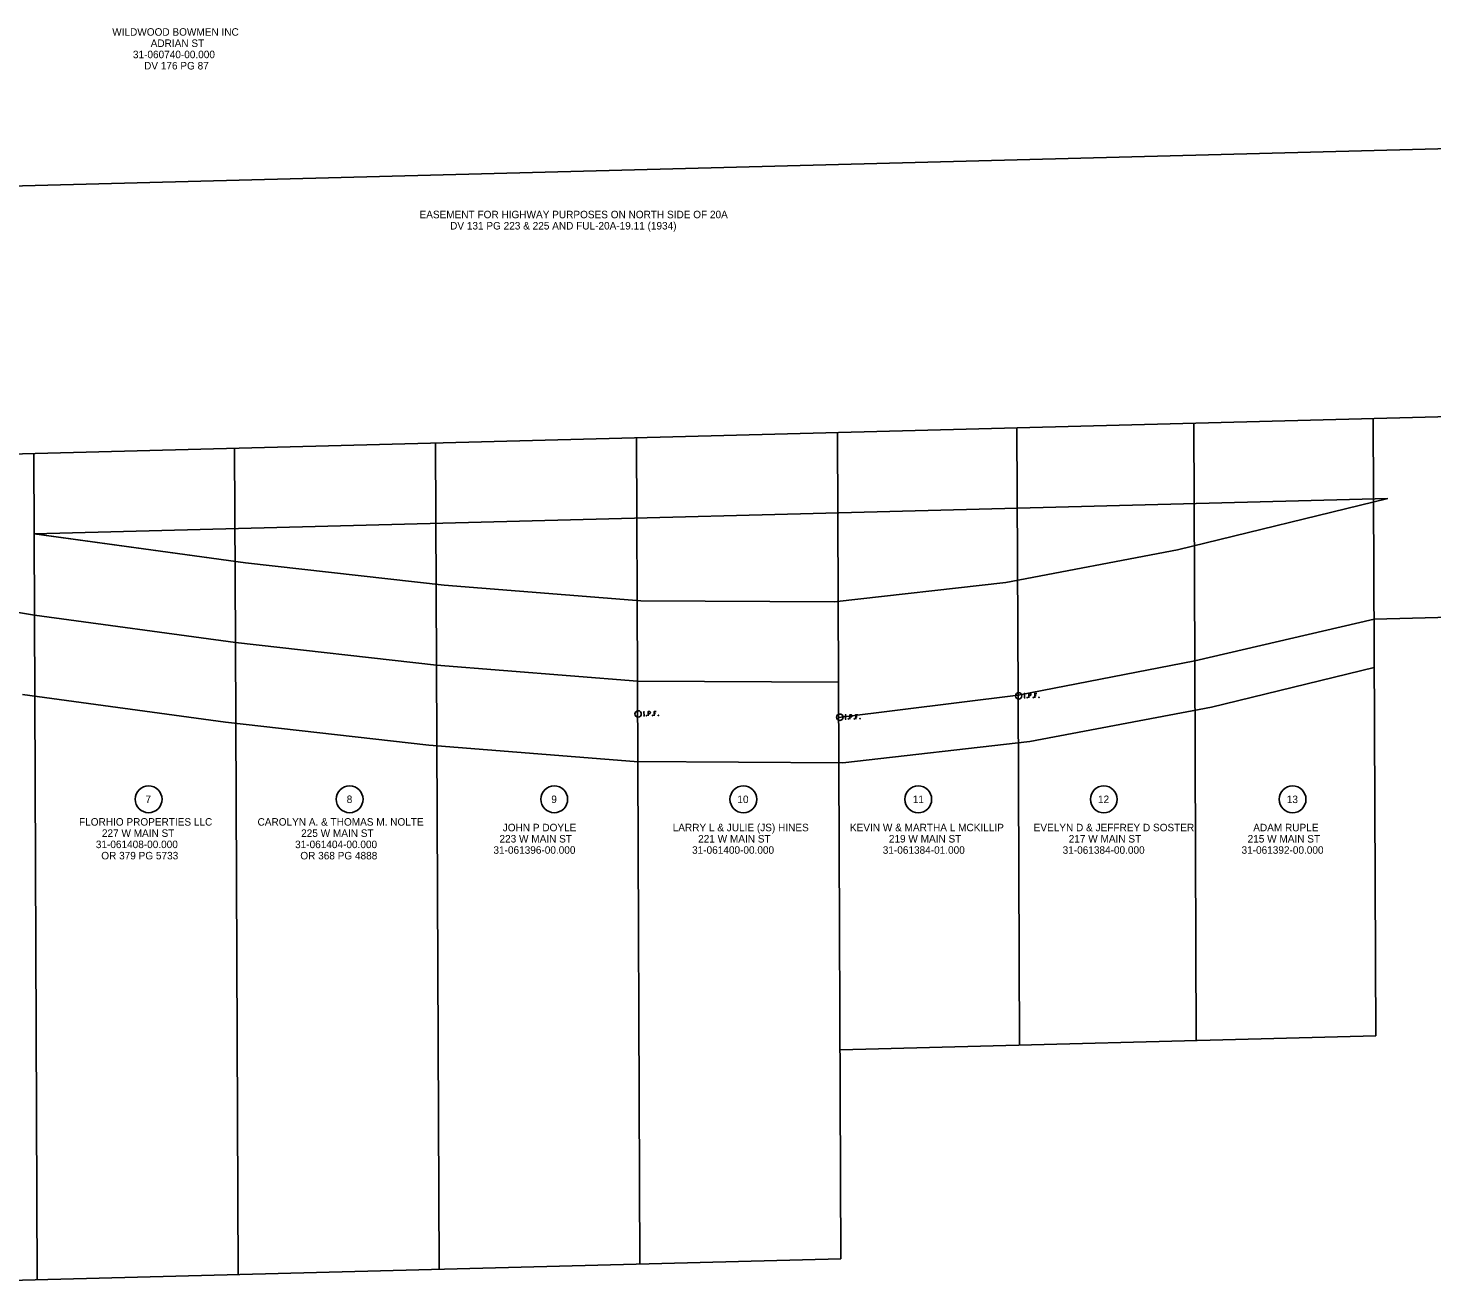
# Model space of a CAD drawing. Extents: x 200073 to 202746, y 352381 to 357578.
# Drawn here: x 200912 to 201436, y 354649 to 355118 of the extents above; entities that cross this region are included whole.
import ezdxf

# ---------------------------------------------------------------- set-up
doc = ezdxf.new("R2010")
doc.units = 0
for name, color, linetype in [('_CIVIL_CONSTRUCTION', 7, 'Continuous'), ('RW_X_CL_100_Bearings', 7, 'Continuous'), ('RW_X_CL_100_Cardinal_Points', 7, 'Continuous'), ('RW_X_CL_100_Stations', 7, 'Continuous'), ('RW_X_CL_500_Bearings', 7, 'Continuous'), ('RW_X_CL_500_Cardinal_Points', 7, 'Continuous'), ('SC_Scratch1', 7, 'Continuous')]:
    doc.layers.add(name, color=color, linetype=linetype)

msp = doc.modelspace()

# ---------------------------------------------------------------- linework, layer by layer
at = {"layer": '_CIVIL_CONSTRUCTION'}
msp.add_line((200083.32, 354937.76), (202745.29, 355007.24), dxfattribs=at)
at = {"layer": 'RW_X_CL_100_Bearings'}
for p, q in [((201281.24, 354869.21), (201280.81, 354969.01)), ((201346.79, 354970.74), (201347.17, 354882.08)), ((201413.77, 354972.48), (201414.76, 354742.08)), ((201138.85, 354965.31), (201139.24, 354874.46)), ((201213.83, 354967.27), (201214.23, 354874.06)), ((200913.92, 354959.44), (200914.18, 354899.14)), ((200988.9, 354961.4), (200989.21, 354888.89)), ((201063.87, 354963.35), (201064.23, 354880.45)), ((200839.14, 354911.48), (200914.18, 354899.14)), ((200914.18, 354899.14), (200915.24, 354651.13)), ((200914.18, 354899.14), (200989.21, 354888.89)), ((201347.17, 354882.08), (201414.09, 354897.58)), ((200989.21, 354888.89), (200990.22, 354653.08)), ((200989.21, 354888.89), (201064.23, 354880.45)), ((201064.23, 354880.45), (201065.19, 354655.04)), ((201064.23, 354880.45), (201139.24, 354874.46)), ((201347.17, 354882.08), (201281.24, 354869.21)), ((201347.17, 354882.08), (201347.78, 354740.33)), ((201139.24, 354874.46), (201140.17, 354657)), ((201139.24, 354874.46), (201214.23, 354874.06)), ((201214.23, 354874.06), (201215.15, 354658.95)), ((201281.24, 354869.21), (201214.29, 354860.86)), ((201281.8, 354738.61), (201281.24, 354869.21)), ((201414.76, 354742.08), (201214.82, 354736.86)), ((201215.15, 354658.95), (200840.26, 354649.17))]:
    msp.add_line(p, q, dxfattribs=at)
at = {"layer": 'RW_X_CL_100_Cardinal_Points'}
for p, q in [((201414.09, 354897.58), (201637.62, 354903.42)), ((201414.17, 354879.62), (201414.09, 354897.58))]:
    msp.add_line(p, q, dxfattribs=at)
at = {"layer": 'RW_X_CL_100_Stations'}
for centre in [(200956.8, 354830.39), (201031.82, 354830.39), (201108.17, 354830.39), (201178.75, 354830.38), (201244, 354830.38), (201313.25, 354830.38), (201383.69, 354830.38)]:
    msp.add_circle(centre, 5, dxfattribs=at)
at = {"layer": 'RW_X_CL_500_Bearings'}
for p, q in [((200731.62, 355054.72), (201543.51, 355075.91)), ((200914.06, 354929.43), (201419.25, 354942.62)), ((201340.76, 354923.48), (201419.24, 354942.62)), ((201340.76, 354923.48), (201419.24, 354942.62)), ((200914.06, 354929.43), (200992.91, 354918.67)), ((200914.74, 354929.45), (200918.64, 354928.81)), ((200918.64, 354928.81), (200992.91, 354918.67)), ((201276.7, 354911.3), (201340.76, 354923.48)), ((201276.7, 354911.3), (201340.76, 354923.48)), ((200992.91, 354918.67), (201067.1, 354910.32)), ((200992.91, 354918.67), (201067.1, 354910.32)), ((201212.62, 354904.07), (201276.7, 354911.3)), ((201212.62, 354904.07), (201276.7, 354911.3)), ((201067.1, 354910.32), (201140.52, 354904.45)), ((201067.1, 354910.32), (201140.52, 354904.45)), ((201140.52, 354904.45), (201212.62, 354904.07)), ((201140.52, 354904.45), (201212.62, 354904.07)), ((201353.48, 354864.82), (201414.17, 354879.62)), ((200909.71, 354869.47), (200985.5, 354859.12)), ((201285.68, 354851.93), (201353.48, 354864.82)), ((200985.5, 354859.12), (201061.36, 354850.58)), ((201061.36, 354850.58), (201137.97, 354844.46)), ((201215.84, 354844.05), (201285.68, 354851.93)), ((201137.97, 354844.46), (201215.84, 354844.05))]:
    msp.add_line(p, q, dxfattribs=at)
at = {"layer": 'SC_Scratch1'}
for points in [[(201283.48, 354869.82), (201283.84, 354869.83)], [(201283.69, 354868.23), (201283.66, 354869.83)], [(201285.26, 354868.26), (201285.23, 354869.86), (201285.75, 354869.87), (201285.81, 354869.85), (201285.89, 354869.83), (201285.92, 354869.81), (201285.95, 354869.78), (201286, 354869.72), (201286.03, 354869.66), (201286.06, 354869.56), (201286.06, 354869.41), (201286.05, 354869.35), (201286.03, 354869.28), (201285.99, 354869.19), (201285.94, 354869.15), (201285.91, 354869.13), (201285.86, 354869.1), (201285.77, 354869.08), (201285.24, 354869.07)], [(201288.23, 354869.91), (201287.47, 354869.9), (201287.5, 354868.3)], [(201287.49, 354869.12), (201288.03, 354869.13)], [(201283.51, 354868.22), (201283.87, 354868.23)], [(201284.65, 354868.46), (201284.7, 354868.46), (201284.73, 354868.44), (201284.77, 354868.39), (201284.77, 354868.32), (201284.74, 354868.27), (201284.71, 354868.25), (201284.65, 354868.24), (201284.62, 354868.27), (201284.58, 354868.32), (201284.58, 354868.38), (201284.61, 354868.43), (201284.65, 354868.46)], [(201286.89, 354868.5), (201286.95, 354868.5), (201286.98, 354868.48), (201287.02, 354868.43), (201287.02, 354868.36), (201286.99, 354868.31), (201286.95, 354868.29), (201286.9, 354868.29), (201286.86, 354868.31), (201286.83, 354868.36), (201286.83, 354868.42), (201286.86, 354868.48), (201286.89, 354868.5)], [(201289.04, 354868.54), (201289.1, 354868.54), (201289.13, 354868.52), (201289.17, 354868.47), (201289.17, 354868.41), (201289.14, 354868.35), (201289.1, 354868.33), (201289.05, 354868.33), (201289.01, 354868.35), (201288.98, 354868.4), (201288.98, 354868.47), (201289.01, 354868.52), (201289.04, 354868.54)], [(201141.46, 354863.07), (201141.81, 354863.08)], [(201141.49, 354861.47), (201141.84, 354861.48)], [(201141.67, 354861.48), (201141.64, 354863.08)], [(201142.62, 354861.71), (201142.68, 354861.71), (201142.71, 354861.69), (201142.74, 354861.64), (201142.74, 354861.57), (201142.71, 354861.52), (201142.68, 354861.5), (201142.62, 354861.5), (201142.59, 354861.52), (201142.56, 354861.57), (201142.56, 354861.63), (201142.59, 354861.68), (201142.62, 354861.71)], [(201143.23, 354861.51), (201143.2, 354863.11), (201143.73, 354863.12), (201143.78, 354863.1), (201143.86, 354863.08), (201143.9, 354863.06), (201143.93, 354863.03), (201143.97, 354862.97), (201144.01, 354862.91), (201144.03, 354862.81), (201144.04, 354862.66), (201144.03, 354862.61), (201144.01, 354862.53), (201143.96, 354862.44), (201143.92, 354862.4), (201143.89, 354862.38), (201143.83, 354862.35), (201143.74, 354862.34), (201143.22, 354862.33)], [(201144.87, 354861.75), (201144.92, 354861.75), (201144.96, 354861.73), (201144.99, 354861.68), (201144.99, 354861.62), (201144.96, 354861.56), (201144.93, 354861.54), (201144.87, 354861.54), (201144.84, 354861.56), (201144.81, 354861.61), (201144.8, 354861.68), (201144.84, 354861.73), (201144.87, 354861.75)], [(201146.21, 354863.16), (201145.45, 354863.15), (201145.48, 354861.55)], [(201145.46, 354862.37), (201146, 354862.38)], [(201147.02, 354861.79), (201147.07, 354861.79), (201147.11, 354861.77), (201147.14, 354861.72), (201147.14, 354861.66), (201147.11, 354861.61), (201147.08, 354861.58), (201147.02, 354861.58), (201146.99, 354861.6), (201146.95, 354861.65), (201146.95, 354861.72), (201146.99, 354861.77), (201147.02, 354861.79)], [(201216.71, 354861.85), (201217.06, 354861.86)], [(201216.74, 354860.25), (201217.09, 354860.26)], [(201216.91, 354860.26), (201216.88, 354861.86)], [(201217.87, 354860.49), (201217.92, 354860.49), (201217.96, 354860.47), (201217.99, 354860.42), (201217.99, 354860.35), (201217.96, 354860.3), (201217.93, 354860.28), (201217.87, 354860.28), (201217.84, 354860.3), (201217.81, 354860.35), (201217.8, 354860.41), (201217.84, 354860.46), (201217.87, 354860.49)], [(201218.48, 354860.29), (201218.45, 354861.89), (201218.98, 354861.9), (201219.03, 354861.88), (201219.11, 354861.86), (201219.15, 354861.84), (201219.18, 354861.81), (201219.22, 354861.75), (201219.26, 354861.69), (201219.28, 354861.59), (201219.28, 354861.44), (201219.27, 354861.39), (201219.25, 354861.31), (201219.21, 354861.22), (201219.17, 354861.18), (201219.14, 354861.16), (201219.08, 354861.13), (201218.99, 354861.12), (201218.46, 354861.11)], [(201220.12, 354860.53), (201220.17, 354860.53), (201220.21, 354860.51), (201220.24, 354860.46), (201220.24, 354860.4), (201220.21, 354860.34), (201220.18, 354860.32), (201220.12, 354860.32), (201220.09, 354860.34), (201220.05, 354860.39), (201220.05, 354860.46), (201220.09, 354860.51), (201220.12, 354860.53)], [(201221.46, 354861.94), (201220.7, 354861.93), (201220.73, 354860.33)], [(201220.71, 354861.15), (201221.25, 354861.16)], [(201222.27, 354860.57), (201222.32, 354860.57), (201222.36, 354860.55), (201222.39, 354860.5), (201222.39, 354860.44), (201222.36, 354860.39), (201222.33, 354860.36), (201222.27, 354860.36), (201222.24, 354860.38), (201222.2, 354860.43), (201222.2, 354860.5), (201222.23, 354860.55), (201222.27, 354860.57)]]:
    msp.add_lwpolyline(points, dxfattribs=at)
for centre in [(201281.49, 354868.98), (201139.46, 354862.24), (201214.71, 354861.02)]:
    msp.add_circle(centre, 1.2, dxfattribs=at)

# ---------------------------------------------------------------- texts
at = {"layer": 'RW_X_CL_100_Stations'}
for s, p in [('WILDWOOD BOWMEN INC', (200943.22, 355115.34)), ('ADRIAN ST', (200957.57, 355111.14)), ('31-060740-00.000', (200950.94, 355106.94)), ('DV 176 PG 87', (200955.11, 355102.74))]:
    msp.add_text(s, height=2.8, dxfattribs=at).set_placement(p)
for s, p in [('7', (200955.62, 354828.99)), ('8', (201030.72, 354828.99)), ('9', (201107.08, 354828.99)), ('10', (201176.52, 354828.98)), ('11', (201241.97, 354828.98)), ('12', (201311.08, 354828.98)), ('13', (201381.54, 354828.98)), ('FLORHIO PROPERTIES LLC', (200930.83, 354820.57)), ('CAROLYN A. & THOMAS M. NOLTE', (200997.45, 354820.56)), ('227 W MAIN ST', (200939.37, 354816.37)), ('225 W MAIN ST', (201013.72, 354816.36)), ('223 W MAIN ST', (201087.74, 354814.26)), ('JOHN P DOYLE', (201088.96, 354818.46)), ('LARRY L & JULIE (JS) HINES', (201152.37, 354818.46)), ('221 W MAIN ST', (201161.87, 354814.26)), ('KEVIN W & MARTHA L MCKILLIP', (201218.53, 354818.46)), ('219 W MAIN ST', (201233.04, 354814.26)), ('EVELYN D & JEFFREY D SOSTER', (201287.08, 354818.46)), ('217 W MAIN ST', (201300.16, 354814.26)), ('215 W MAIN ST', (201366.92, 354814.26)), ('ADAM RUPLE', (201369.02, 354818.45)), ('31-061408-00.000', (200937.1, 354812.17)), ('31-061404-00.000', (201011.46, 354812.16)), ('31-061396-00.000', (201085.48, 354810.06)), ('31-061400-00.000', (201159.61, 354810.06)), ('31-061384-01.000', (201230.77, 354810.06)), ('31-061384-00.000', (201297.89, 354810.06)), ('31-061392-00.000', (201364.65, 354810.06)), ('OR 379 PG 5733', (200939.13, 354807.97)), ('OR 368 PG 4888', (201013.41, 354807.96))]:
    msp.add_text(s, height=2.8, rotation=359.9985, dxfattribs=at).set_placement(p)
at = {"layer": 'RW_X_CL_500_Cardinal_Points'}
for s, p in [('EASEMENT FOR HIGHWAY PURPOSES ON NORTH SIDE OF 20A', (201057.89, 355047.22)), ('DV 131 PG 223 & 225 AND FUL-20A-19.11 (1934)', (201069.31, 355043.02))]:
    msp.add_text(s, height=2.8, dxfattribs=at).set_placement(p)

doc.saveas('drawing.dxf')
